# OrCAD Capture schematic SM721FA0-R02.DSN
size C
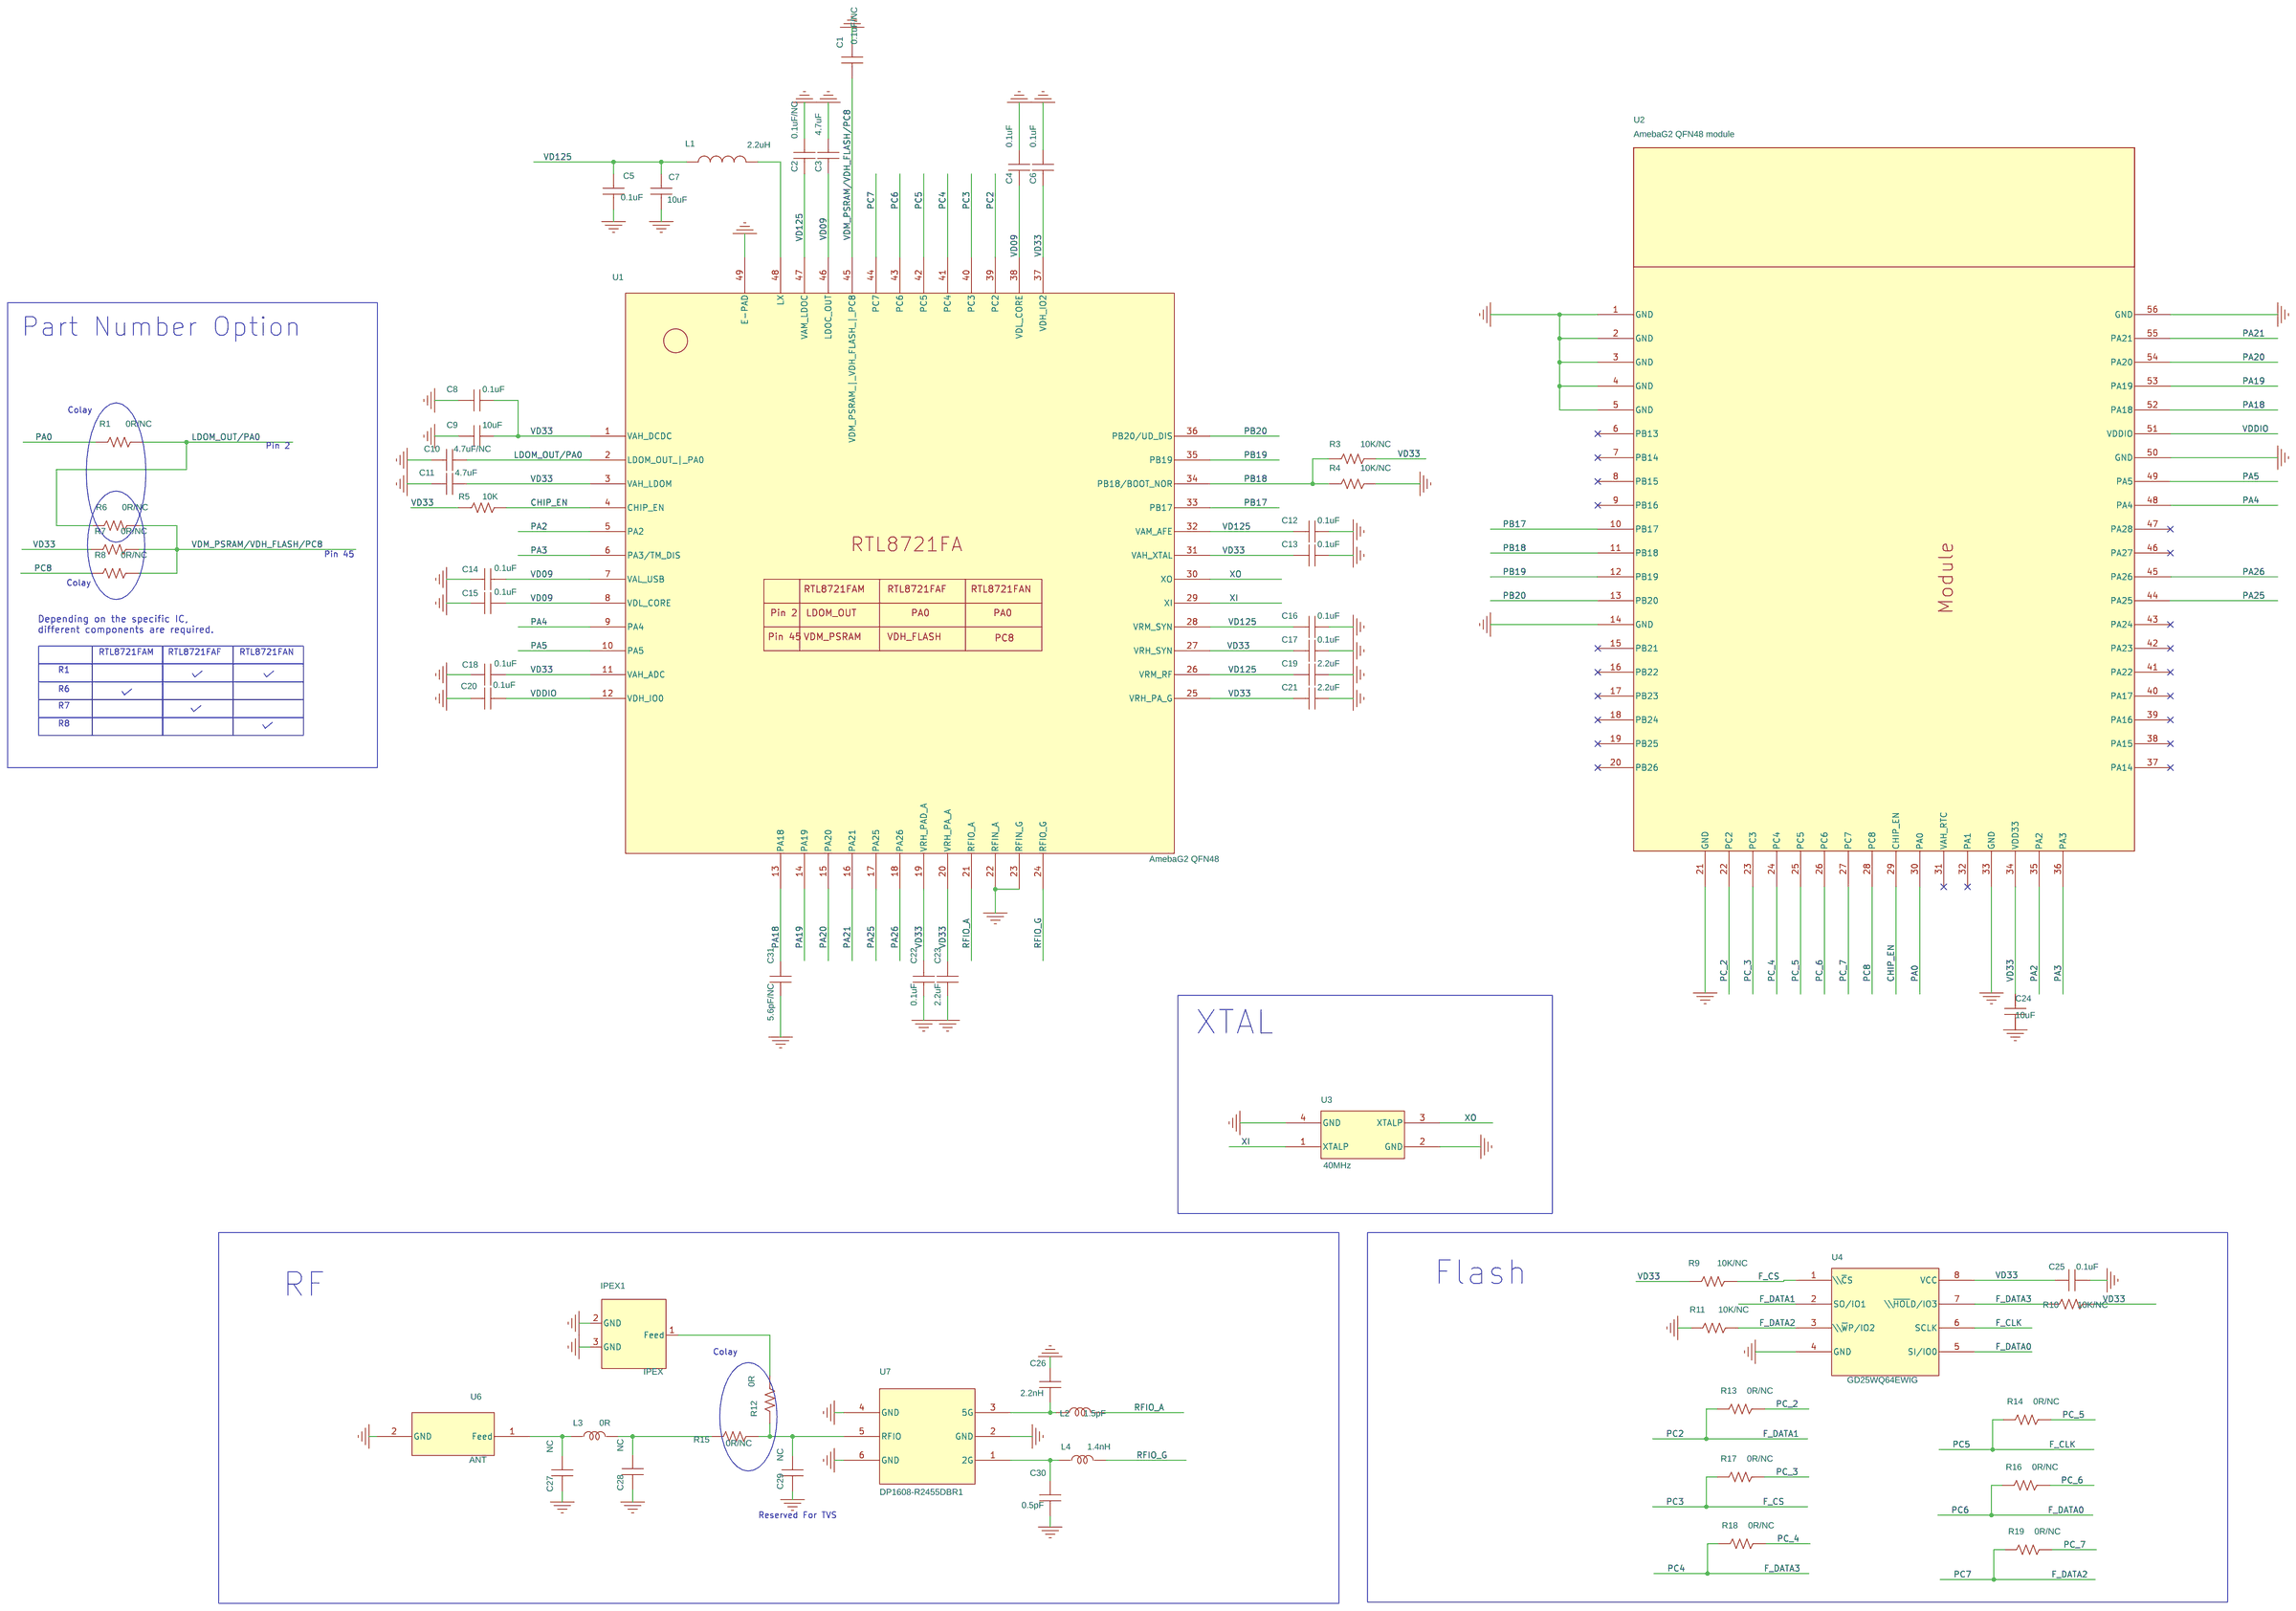
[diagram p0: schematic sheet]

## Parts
C1  0.1uF/NC  [C0201]
C2  0.1uF/NC  [C0201]
C3  4.7uF  [C0402]
C4  0.1uF  [C0201]
C5  0.1uF  [C0201]
C6  0.1uF  [C0201]
C7  10uF  [C0402]
C8  0.1uF  [C0201]
C9  10uF  [C0402]
C10  4.7uF/NC  [C0402]
C11  4.7uF  [C0402]
C12  0.1uF  [C0201]
C13  0.1uF  [C0201]
C14  0.1uF  [C0201]
C15  0.1uF  [C0201]
C16  0.1uF  [C0201]
C17  0.1uF  [C0201]
C18  0.1uF  [C0201]
C19  2.2uF  [C0402]
C20  0.1uF  [C0201]
C21  2.2uF  [C0402]
C22  0.1uF  [C0201]
C23  2.2uF  [C0402]
C24  10uF  [C0402]
C25  0.1uF  [C0201]
C26  2.2nH  [C0201]
C27  NC  [C0201]
C28  NC  [C0201]
C29  NC  [C0201]
C30  0.5pF  [C0201]
C31  5.6pF/NC  [C0201]
IPEX1  IPEX  [IPEX3-1.35-0.7X2.2]
L1  2.2uH  [L2016]
L2  1.5pF  [L0201]
L3  0R  [L0201]
L4  1.4nH  [L0201]
R1  0R/NC  [R0201]
R3  10K/NC  [R0201]
R4  10K/NC  [R0201]
R5  10K  [R0201]
R6  0R/NC  [R0201]
R7  0R/NC  [R0201]
R8  0R/NC  [R0201]
R9  10K/NC  [R0201]
R10  10K/NC  [R0201]
R11  10K/NC  [R0201]
R12  0R  [R0201]
R13  0R/NC  [R0201]
R14  0R/NC  [R0201]
R15  0R/NC  [R0201]
R16  0R/NC  [R0201]
R17  0R/NC  [R0201]
R18  0R/NC  [R0201]
R19  0R/NC  [R0201]
U1  AmebaG2 QFN48  [QFN48-0.4-6X6-EP4.7]
U2  AmebaG2 QFN48 module  [MODULE56-18X28]
U3  40MHz  [XTAL-2016]
U4  GD25WQ64EWIG  [SOIC8-1.27-150-0.6X1.4]
U6  ANT  [G2_PANT]
U7  DP1608-R2455DBR1  [DPX1608-6-0.5-0.25X0.6]

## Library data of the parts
C1 C4 C6 C12 C13 C16 C17 C19 C21-C23 C31 = CAPACITOR_NON-POL_0: Part Number: 0402X225K250CT; Part Type: Ceramic; Tolerance,Voltage,Dielectric,Lead Free(Y/N): ±10%,25V,X5R; Datasheet: \\172.29.17.1\cn\WLAN\WLAN2\boarddesignLIB\93_component_database\Datasheet\Capacitor\Capacitor_Walsin_MLCC.pdf
C2 C3 C8-C11 C24 = CAPACITOR_NON-POL_0: Part Number: 0402X475M160CT; Part Type: Ceramic; Tolerance,Voltage,Dielectric,Lead Free(Y/N): ±20%,16V,X5R; Datasheet: \\172.29.17.1\cn\WLAN\WLAN2\boarddesignLIB\147_component_database\Datasheet\Capacitor\Capacitor_Walsin_MLCC.pdf
C5 C25 = CAPACITOR_NON-POL_0: ±10%,25V,X5R; Manufacturer: WALSIN; Part Number: 0201X104K250CT; Voltage: 25V; Datasheet: \\172.29.17.1\cn\WLAN\WLAN2\boarddesignLIB\05_component_database\Datasheet\Capacitor\Capacitor_Walsin_MLCC.pdf
C7 = CAPACITOR_NON-POL_0: ±20%,10V,X5R; Manufacturer: WALSIN; Part Number: 0402X106M100CT; Voltage: 10V; Datasheet: \\172.29.17.1\cn\WLAN\WLAN2\boarddesignLIB\53_component_database\Datasheet\Capacitor\Capacitor_Walsin_MLCC.pdf
C14 C15 C18 C20 = CAPACITOR_NON-POL_0: Part Number: 0201X104K100CT; Part Type: Ceramic; Tolerance,Voltage,Dielectric,Lead Free(Y/N): ±10%，10V，X5R; Datasheet: \\172.29.17.1\cn\WLAN\WLAN2\boarddesignLIB\04_component_database\Datasheet\Capacitor\Capacitor_Walsin_MLCC.pdf
C26-C30 = CAPACITOR_NON-POL_0: +/-0.1pF,25V,NPO,Y; Manufacturer: WALSIN; Part Number: RF03N1R2B250CT; Voltage: 25V; Datasheet: \\172.29.17.1\cn\WLAN\WLAN2\boarddesignLIB\31_component_database\Datasheet\Capacitor\Capacitor_Walsin_MLCC.pdf
IPEX1 = TP_0: IPEX大头，IPEX1; Manufacturer: Argosy; Part Number: RFCSR-N3300-TP40; Datasheet: \\172.29.17.1\cn\WLAN\WLAN2\boarddesignLIB\01_component_database\Datasheet\Connector\RF Connector_Argosy_RFCSR-N3300-TP40_APL_Realtek (2017-03-06).pdf
L1 = Inductor_Power: ±20%; Manufacturer: TAIYO YUDEN; Part Number: MAKK2016T2R2M; Datasheet: \\172.29.17.1\cn\WLAN\WLAN2\boarddesignLIB\01_component_database\Datasheet\Inductor\Power Inductor_Taiyo_MAKK2016T2R2M_SS.pdf
L2-L4 = Inductor_RF: ±0.3nH,4min; Manufacturer: CHILISIN; Part Number: CLH0603T-1N0S-F
R1 R3 R4 R6-R8 R12-R19 = RES_0: JUMPER; Manufacturer: WALSIN; Part Number: WR02X000PTL; Datasheet: \\172.29.17.1\cn\WLAN\WLAN2\boarddesignLIB\01_component_database\Datasheet\Resistor\Resistor_Walsin_chipR.pdf
R5 = RES_0: Part Number: WR02X103 JAL; Tolerance,Voltage,Dielectric,Lead Free(Y/N): +/-5%; Datasheet: \\172.29.17.1\cn\WLAN\WLAN2\boarddesignLIB\40_component_database\Datasheet\Resistor\Resistor_Walsin_chipR.pdf
R9-R11 = RES_0: +/-1%; Manufacturer: WALSIN; Part Number: WR02X1002FAL; Datasheet: \\172.29.17.1\cn\WLAN\WLAN2\boarddesignLIB\01_component_database\Datasheet\Resistor\Resistor_Walsin_chipR.pdf
U1 = RL7005_QFN48: RL7005 QFN48; Manufacturer: Realtek
U2 = Amebagreen2_Module_7
U3 = XTAL_0: 9pf，25ohms，10ppm，-55-125度; Part Number: E1SB40E00090FE
U4 = Flash_0: Used for Module; Part Number: GD25Q16C; Datasheet: \\172.29.17.1\cn\WLAN\WLAN2\boarddesignLIB\01_component_database\Datasheet\Memory\FLASH_GigaDevice_GD25Q16CTIG.pdf
U6 = ANT
U7 = DPX_1: Manufacturer: ACX; Datasheet: \\172.29.17.1\cn\WLAN\WLAN2\boarddesignLIB\01_component_database\Datasheet\RF Chip\DPX_ACX_DP1608-R2455DBR1_Preliminary_S-R00-N1823_1.pdf

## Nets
GND: C1.1 C2.1 C3.1 C4.1 C5.2 C6.1 C7.2 C8.2 C9.2 C10.2 C11.2 C12.1 C13.1 C14.1 C15.1 C16.1 C17.1 C18.1 C19.1 C20.1 C21.1 C22.1 C23.1 C24.2 C25.2 C26.1 C27.2 C28.2 C29.2 C30.2 C31.1 IPEX1.2(GND) IPEX1.3(GND) R4.1 R11.1 U1.22(RFIN_A) U1.23(RFIN_G) U1.49(E-PAD) U2.1(GND) U2.2(GND) U2.3(GND) U2.4(GND) U2.5(GND) U2.14(GND) U2.21(GND) U2.33(GND) U2.50(GND) U2.56(GND) U3.2(GND) U3.4(GND) U4.4(GND) U6.2(GND) U7.2(GND) U7.4(GND) U7.6(GND)
VDDIO: C20.2 U1.12(VDH_IO0) U2.51(VDDIO)
CHIP_EN: R5.1 U1.4(CHIP_EN) U2.29(CHIP_EN)
F_CLK: R14.1 U1.42(PC5) U4.6(SCLK)
F_CS: R9.2 R17.1 U1.40(PC3) U4.1(\\~{C}S)
F_DATA0: R16.1 U1.43(PC6) U4.5(SI/IO0)
F_DATA1: R13.1 U1.39(PC2) U4.2(SO/IO1)
F_DATA2: R11.2 R19.1 U1.44(PC7) U4.3(\\~{W}P/IO2)
F_DATA3: R10.1 R18.1 U1.41(PC4) U4.7(\\~{HOL}D/IO3)
LDOM_OUT/PA0: C10.1 R1.2 R6.1 U1.2(LDOM_OUT_|_PA0)
PA0: R1.1 U2.30(PA0)
PA2: U1.5(PA2) U2.35(PA2)
PA3: U1.6(PA3/TM_DIS) U2.36(PA3)
PA4: U1.9(PA4) U2.48(PA4)
PA5: U1.10(PA5) U2.49(PA5)
PA18: C31.2 U1.13(PA18) U2.52(PA18)
PA19: U1.14(PA19) U2.53(PA19)
PA20: U1.15(PA20) U2.54(PA20)
PA21: U1.16(PA21) U2.55(PA21)
PA25: U1.17(PA25) U2.44(PA25)
PA26: U1.18(PA26) U2.45(PA26)
PB17: U1.33(PB17) U2.10(PB17)
PB18: R3.2 R4.2 U1.34(PB18/BOOT_NOR) U2.11(PB18)
PB19: U1.35(PB19) U2.12(PB19)
PB20: U1.36(PB20/UD_DIS) U2.13(PB20)
PC8: R8.1 U2.28(PC8)
PC_2: R13.2 U2.22(PC2)
PC_3: R17.2 U2.23(PC3)
PC_4: R18.2 U2.24(PC4)
PC_5: R14.2 U2.25(PC5)
PC_6: R16.2 U2.26(PC6)
PC_7: R19.2 U2.27(PC7)
RFIO_A: L2.2 U1.21(RFIO_A)
RFIO_G: L4.2 U1.24(RFIO_G)
VD09: C3.2 C4.2 C14.2 C15.2 U1.7(VAL_USB) U1.8(VDL_CORE) U1.38(VDL_CORE) U1.46(LDOC_OUT)
VD33: C6.2 C8.1 C9.1 C11.1 C13.2 C17.2 C18.2 C21.2 C22.2 C23.2 C24.1 C25.1 R3.1 R5.2 R7.1 R9.1 R10.2 U1.1(VAH_DCDC) U1.3(VAH_LDOM) U1.11(VAH_ADC) U1.19(VRH_PAD_A) U1.20(VRH_PA_A) U1.25(VRH_PA_G) U1.27(VRH_SYN) U1.31(VAH_XTAL) U1.37(VDH_IO2) U2.34(VDD33) U4.8(VCC)
VD125: C2.2 C5.1 C7.1 C12.2 C16.2 C19.2 L1.1 U1.26(VRM_RF) U1.28(VRM_SYN) U1.32(VAM_AFE) U1.47(VAM_LDOC)
VDM_PSRAM/VDH_FLASH/PC8: C1.2 R6.2 R7.2 R8.2 U1.45(VDM_PSRAM_|_VDH_FLASH_|_PC8)
XI: U1.29(XI) U3.1(XTALP)
XO: U1.30(XO) U3.3(XTALP)
N16477691: C26.2 L2.1 U7.3(5G)
N16477831: C29.1 R12.1 R15.2 U7.5(RFIO)
N16477975: IPEX1.1(Feed) R12.2
N16478039: C28.1 L3.2 R15.1
N16478047: C27.1 L3.1 U6.1(Feed)
N16496117: C30.1 L4.1 U7.1(2G)
N16496137: L1.2 U1.48(LX)

Not connected (* = marked no-connect by the designer): U2 6(PB13)* 7(PB14)* 8(PB15)* 9(PB16)* 15(PB21)* 16(PB22)* 17(PB23)* 18(PB24)* 19(PB25)* 20(PB26)* 31(VAH_RTC)* 32(PA1)* 37(PA14)* 38(PA15)* 39(PA16)* 40(PA17)* 41(PA22)* 42(PA23)* 43(PA24)* 46(PA27)* 47(PA28)*

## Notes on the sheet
- Part Number Option
- Colay
- Pin 2
- Pin 45
- Colay
- Depending on the specific IC,
  different components are required.
- RTL8721FAM
- RTL8721FAF
- RTL8721FAN
- R1
- R6
- R7
- R8
- XTAL
- Flash
- RF
- Colay
- Reserved For TVS
